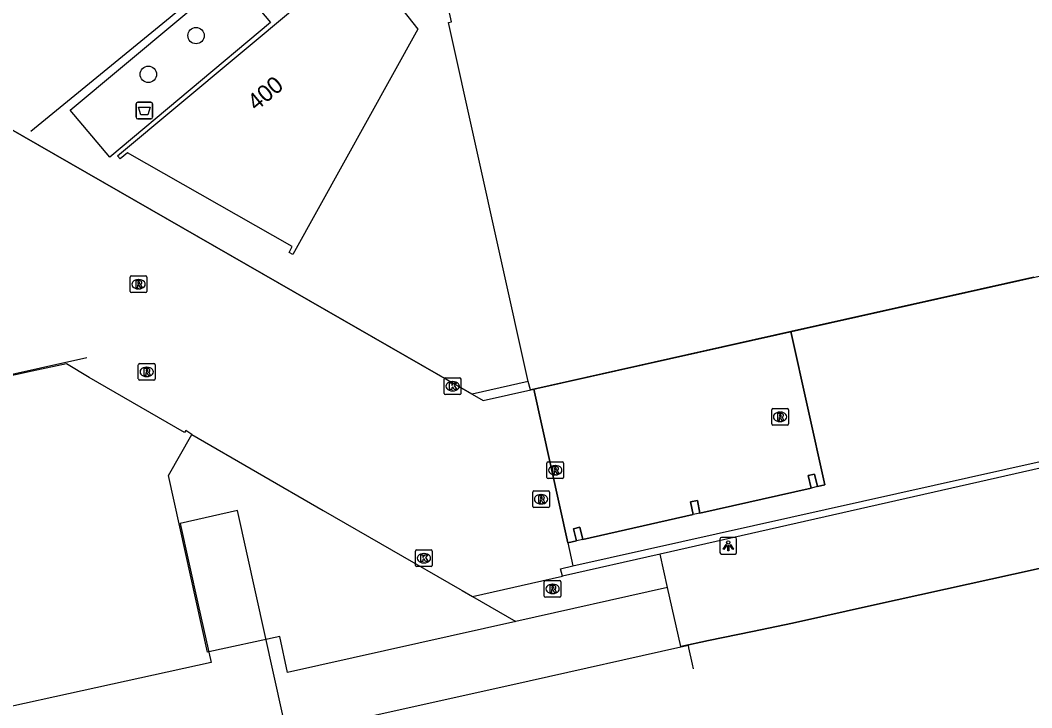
# Model space of a CAD drawing. Extents: x 160806 to 161707, y 383697 to 384148.
# Drawn here: x 161428.9 to 161489.3, y 383818.3 to 383859.4 of the extents above; entities that cross this region are included whole.
import ezdxf

# ---------------------------------------------------------------- set-up
doc = ezdxf.new("R2010")
doc.units = 0
for name, color, linetype in [('IMGEO_Afvalbak', 7, 'Continuous'), ('IMGEO_Boom', 7, 'Continuous'), ('IMGEO_Hek', 7, 'Continuous'), ('IMGEO_Kolk', 7, 'Continuous'), ('IMGEO_Lichtpunt', 7, 'Continuous'), ('IMGEO_Lijnafwatering', 7, 'Continuous'), ('IMGEO_Pand', 7, 'Continuous'), ('IMGEO_Pand_nummerreeks', 7, 'Continuous'), ('IMGEO_Pand_overbouw', 7, 'Continuous'), ('IMGEO_Pand_vergunning_verleend', 7, 'Continuous'), ('IMGEO_Rijbaan_lokaal_gesloten', 7, 'Continuous'), ('IMGEO_Rijbaan_lokaal_open', 7, 'Continuous'), ('IMGEO_Rioolput', 7, 'Continuous'), ('IMGEO_Spoorbaan_halfverhard', 7, 'Continuous'), ('IMGEO_Verkeerseiland_open', 7, 'Continuous'), ('IMGEO_Voetpad_open', 7, 'Continuous')]:
    doc.layers.add(name, color=color, linetype=linetype)

msp = doc.modelspace()

# ---------------------------------------------------------------- linework, layer by layer
at = {"layer": 'IMGEO_Afvalbak'}
for p, q in [((161435.802, 383853.602), (161435.802, 383854.402)), ((161435.802, 383854.402), (161435.802, 383853.602)), ((161435.902, 383854.502), (161436.692, 383854.502)), ((161436.692, 383854.502), (161435.902, 383854.502)), ((161436.792, 383854.402), (161436.792, 383853.602)), ((161436.792, 383853.602), (161436.792, 383854.402)), ((161436.692, 383853.502), (161435.902, 383853.502)), ((161435.902, 383853.502), (161436.692, 383853.502))]:
    msp.add_line(p, q, dxfattribs=at)
msp.add_lwpolyline([(161435.945, 383854.216), (161436.649, 383854.216), (161436.5, 383853.746), (161436.094, 383853.746), (161435.945, 383854.216)], dxfattribs=at)
for centre, start, end in [((161435.902, 383854.402), 90, 180), ((161435.902, 383854.402), 90, 180), ((161436.692, 383854.402), 0, 90), ((161436.692, 383854.402), 360, 90), ((161435.902, 383853.602), 180, 270), ((161435.902, 383853.602), 180, 270), ((161436.692, 383853.602), 270, 0), ((161436.692, 383853.602), 270, 0)]:
    msp.add_arc(centre, 0.1, start, end, dxfattribs=at)
at = {"layer": 'IMGEO_Boom'}
for centre in [(161439.388, 383858.484), (161436.538, 383856.171)]:
    msp.add_circle(centre, 0.489, dxfattribs=at)
at = {"layer": 'IMGEO_Hek'}
for points in [[(161468.352, 383821.972), (161470.021, 383822.345), (161472.634, 383822.879), (161475.023, 383823.371), (161479.934, 383824.467), (161509.272, 383830.942), (161514.217, 383832.035), (161521.635, 383833.723), (161580.201, 383846.689), (161582.51, 383847.687), (161585.012, 383847.75), (161614.342, 383854.325), (161641.301, 383860.274), (161651.06, 383862.411), (161662.497, 383864.892), (161670.593, 383866.669), (161682.93, 383869.376), (161687.731, 383870.454), (161692.46, 383871.911), (161696.167, 383872.737)], [(161439.133, 383834.644), (161446.976, 383830.114), (161455.145, 383825.407)], [(161455.145, 383825.407), (161455.299, 383825.318)], [(161455.299, 383825.318), (161455.916, 383824.962)], [(161455.916, 383824.962), (161458.497, 383823.475)], [(161468.36, 383821.937), (161459.292, 383819.913), (161449.186, 383817.657)]]:
    msp.add_lwpolyline(points, dxfattribs=at)
at = {"layer": 'IMGEO_Kolk'}
for p, q in [((161454.221, 383837.106), (161454.221, 383837.958)), ((161454.296, 383838.032), (161455.148, 383838.032)), ((161454.709, 383837.812), (161454.734, 383837.812)), ((161455.222, 383837.958), (161455.222, 383837.106)), ((161454.732, 383837.252), (161454.707, 383837.252)), ((161455.148, 383837.032), (161454.296, 383837.032)), ((161452.506, 383826.829), (161452.506, 383827.681)), ((161452.581, 383827.755), (161453.433, 383827.755)), ((161452.994, 383827.535), (161453.019, 383827.535)), ((161453.507, 383827.681), (161453.507, 383826.829)), ((161453.017, 383826.975), (161452.992, 383826.975)), ((161453.433, 383826.755), (161452.581, 383826.755))]:
    msp.add_line(p, q, dxfattribs=at)
for points in [[(161454.221, 383837.106), (161454.221, 383837.958)], [(161454.296, 383838.032), (161455.148, 383838.032)], [(161454.542, 383837.732), (161454.665, 383837.732), (161454.665, 383837.581), (161454.795, 383837.732), (161454.959, 383837.732), (161454.813, 383837.581), (161454.966, 383837.332), (161454.814, 383837.332), (161454.729, 383837.496), (161454.665, 383837.429), (161454.665, 383837.332), (161454.542, 383837.332), (161454.542, 383837.732)], [(161455.222, 383837.958), (161455.222, 383837.106)], [(161455.148, 383837.032), (161454.296, 383837.032)], [(161452.506, 383826.829), (161452.506, 383827.681)], [(161452.581, 383827.755), (161453.433, 383827.755)], [(161452.827, 383827.455), (161452.95, 383827.455), (161452.95, 383827.304), (161453.08, 383827.455), (161453.244, 383827.455), (161453.098, 383827.304), (161453.251, 383827.055), (161453.099, 383827.055), (161453.014, 383827.219), (161452.95, 383827.152), (161452.95, 383827.055), (161452.827, 383827.055), (161452.827, 383827.455)], [(161453.507, 383827.681), (161453.507, 383826.829)], [(161453.433, 383826.755), (161452.581, 383826.755)]]:
    msp.add_lwpolyline(points, dxfattribs=at)
for centre, start, end in [((161454.298, 383837.956), 91.55205, 178.44795), ((161454.298, 383837.956), 91.55205, 178.44795), ((161455.146, 383837.956), 1.55205, 88.44795), ((161455.146, 383837.956), 1.55205, 88.44795), ((161454.298, 383837.108), 181.55205, 268.44795), ((161454.298, 383837.108), 181.55205, 268.44795), ((161455.146, 383837.108), 271.55205, 358.44795), ((161455.146, 383837.108), 271.55205, 358.44795), ((161452.583, 383827.679), 91.55205, 178.44795), ((161452.583, 383827.679), 91.55205, 178.44795), ((161453.431, 383827.679), 1.55205, 88.44795), ((161453.431, 383827.679), 1.55205, 88.44795), ((161452.583, 383826.831), 181.55205, 268.44795), ((161452.583, 383826.831), 181.55205, 268.44795), ((161453.431, 383826.831), 271.55205, 358.44795), ((161453.431, 383826.831), 271.55205, 358.44795)]:
    msp.add_arc(centre, 0.0765, start, end, dxfattribs=at)
for centre, major_axis, ratio, start_param, end_param in [((161454.708, 383837.532), (-0.387, 0.002), 0.722429, 4.712389, 7.853982), ((161454.733, 383837.532), (-0.39, 0.002), 0.717154, 1.570796, 4.712389), ((161452.993, 383827.255), (-0.387, 0.002), 0.722429, 4.712389, 7.853982), ((161453.018, 383827.255), (-0.39, 0.002), 0.717154, 1.570796, 4.712389)]:
    msp.add_ellipse(centre, major_axis=major_axis, ratio=ratio, start_param=start_param, end_param=end_param, dxfattribs=at)
at = {"layer": 'IMGEO_Lichtpunt'}
for p, q in [((161470.695, 383828.404), (161470.695, 383827.597)), ((161470.695, 383828.404), (161470.695, 383827.597)), ((161471.597, 383828.499), (161470.789, 383828.499)), ((161471.597, 383828.499), (161470.789, 383828.499)), ((161471.691, 383827.597), (161471.691, 383828.404)), ((161471.691, 383827.597), (161471.691, 383828.404)), ((161470.789, 383827.503), (161471.597, 383827.503)), ((161470.789, 383827.503), (161471.597, 383827.503))]:
    msp.add_line(p, q, dxfattribs=at)
for points in [[(161471.069, 383828.068), (161471.108, 383828.04), (161470.92, 383827.778), (161470.882, 383827.805), (161471.069, 383828.068)], [(161471.171, 383828.02), (161471.218, 383828.02), (161471.218, 383827.698), (161471.171, 383827.698), (161471.171, 383828.02)], [(161471.281, 383828.04), (161471.319, 383828.067), (161471.506, 383827.805), (161471.467, 383827.777), (161471.281, 383828.04)]]:
    msp.add_lwpolyline(points, dxfattribs=at)
msp.add_circle((161471.194, 383828.202), 0.0994, dxfattribs=at)
for centre, start, end in [((161470.789, 383828.404), 90, 180), ((161470.789, 383828.404), 90, 180), ((161471.597, 383828.404), 0, 90), ((161471.597, 383828.404), 0, 90), ((161470.789, 383827.597), 180, 270), ((161470.789, 383827.597), 180, 270), ((161471.597, 383827.597), 270, 0), ((161471.597, 383827.597), 270, 360)]:
    msp.add_arc(centre, 0.0946, start, end, dxfattribs=at)
at = {"layer": 'IMGEO_Lijnafwatering'}
for points in [[(161446.281, 383866.489), (161429.508, 383852.763)], [(161419.351, 383836.25), (161432.862, 383839.245)]]:
    msp.add_lwpolyline(points, dxfattribs=at)
at = {"layer": 'IMGEO_Pand'}
for points in [[(161459.23, 383837.816), (161454.467, 383859.266), (161454.649, 383859.314), (161452.306, 383869.965), (161465.897, 383881.096)], [(161445.17, 383845.408), (161444.948, 383845.529), (161445.128, 383845.88), (161435.296, 383851.477), (161434.859, 383851.112), (161434.699, 383851.304), (161449.115, 383863.351), (161452.644, 383858.861), (161445.17, 383845.408)], [(161489.445, 383844.046), (161474.936, 383840.799)], [(161459.571, 383837.36), (161474.936, 383840.799)], [(161439.133, 383834.644), (161439.136, 383834.65), (161438.779, 383834.879), (161438.695, 383834.766), (161432.999, 383838.061), (161431.64, 383838.863), (161429.594, 383838.43), (161405.826, 383833.211)], [(161459.571, 383837.36), (161459.371, 383837.315), (161459.23, 383837.816)], [(161458.497, 383823.475), (161444.86, 383820.431), (161444.389, 383822.588), (161440.151, 383821.653), (161440.079, 383821.637), (161437.743, 383832.2), (161439.133, 383834.644)], [(161476.528, 383831.533), (161476.347, 383832.284), (161475.96, 383832.191), (161476.142, 383831.439)], [(161476.528, 383831.533), (161476.142, 383831.439)], [(161469.504, 383829.954), (161469.353, 383830.703), (161468.944, 383830.62), (161469.095, 383829.871)], [(161469.504, 383829.954), (161469.095, 383829.871)], [(161462.499, 383828.381), (161462.322, 383829.103), (161461.943, 383829.01), (161462.119, 383828.288)], [(161462.499, 383828.381), (161462.119, 383828.288)], [(161467.565, 383825.499), (161458.497, 383823.475)], [(161468.352, 383821.972), (161467.565, 383825.499)], [(161468.352, 383821.972), (161468.36, 383821.937)], [(161468.36, 383821.937), (161459.292, 383819.913), (161449.186, 383817.657)]]:
    msp.add_lwpolyline(points, dxfattribs=at)
at = {"layer": 'IMGEO_Pand_overbouw'}
for points in [[(161576.544, 383863.524), (161556.299, 383953.974), (161403.923, 383918.874), (161417.58, 383859.039), (161456.542, 383836.683)], [(161476.142, 383831.439), (161475.96, 383832.191), (161476.347, 383832.284), (161476.528, 383831.533), (161476.962, 383831.641), (161474.936, 383840.799), (161459.571, 383837.36), (161461.599, 383828.173), (161462.119, 383828.288), (161461.943, 383829.01), (161462.322, 383829.103), (161462.499, 383828.381), (161469.095, 383829.871), (161468.944, 383830.62), (161469.353, 383830.703), (161469.504, 383829.954)], [(161445.142, 383815.339), (161441.873, 383830.1), (161438.438, 383829.334), (161439.521, 383824.478), (161440.29, 383821.029), (161419.78, 383816.517), (161421.083, 383810.599), (161402.46, 383805.86), (161402.903, 383803.833), (161432.009, 383812.432)]]:
    msp.add_lwpolyline(points, close=True, dxfattribs=at)
at = {"layer": 'IMGEO_Pand_vergunning_verleend'}
msp.add_lwpolyline([(161431.877, 383854.037), (161441.49, 383862.083), (161443.842, 383859.273), (161434.229, 383851.226), (161431.877, 383854.037)], dxfattribs=at)
at = {"layer": 'IMGEO_Rijbaan_lokaal_gesloten'}
for points in [[(161461.912, 383826.794), (161498.576, 383834.978), (161578.911, 383853.047)], [(161474.936, 383840.799), (161476.962, 383831.641), (161476.528, 383831.533)], [(161476.142, 383831.439), (161469.504, 383829.954)], [(161469.095, 383829.871), (161462.499, 383828.381)], [(161462.119, 383828.288), (161461.599, 383828.173)], [(161461.599, 383828.173), (161461.912, 383826.794)]]:
    msp.add_lwpolyline(points, dxfattribs=at)
at = {"layer": 'IMGEO_Rijbaan_lokaal_open'}
for points in [[(161459.23, 383837.816), (161455.886, 383837.059), (161417.58, 383859.039), (161418.734, 383860.447)], [(161461.599, 383828.173), (161459.571, 383837.36)], [(161439.133, 383834.644), (161446.976, 383830.114), (161455.145, 383825.407), (161455.299, 383825.318), (161455.916, 383824.962)], [(161461.28, 383826.175), (161461.178, 383826.63), (161461.912, 383826.794)], [(161455.916, 383824.962), (161461.28, 383826.175)]]:
    msp.add_lwpolyline(points, dxfattribs=at)
at = {"layer": 'IMGEO_Rioolput'}
for p, q in [((161435.451, 383843.201), (161435.451, 383844.053)), ((161435.526, 383844.127), (161436.378, 383844.127)), ((161435.939, 383843.907), (161435.964, 383843.907)), ((161436.452, 383844.053), (161436.452, 383843.201)), ((161436.378, 383843.127), (161435.526, 383843.127)), ((161435.962, 383843.347), (161435.937, 383843.347)), ((161436.016, 383838.892), (161436.868, 383838.892)), ((161435.941, 383837.966), (161435.941, 383838.818)), ((161436.429, 383838.672), (161436.454, 383838.672)), ((161436.942, 383838.818), (161436.942, 383837.966)), ((161436.868, 383837.892), (161436.016, 383837.892)), ((161436.452, 383838.112), (161436.427, 383838.112)), ((161473.791, 383835.279), (161473.791, 383836.131)), ((161473.866, 383836.205), (161474.718, 383836.205)), ((161474.279, 383835.985), (161474.304, 383835.985)), ((161474.792, 383836.131), (161474.792, 383835.279)), ((161474.302, 383835.425), (161474.277, 383835.425)), ((161474.718, 383835.205), (161473.866, 383835.205)), ((161460.351, 383832.087), (161460.351, 383832.939)), ((161460.426, 383833.013), (161461.278, 383833.013)), ((161461.352, 383832.939), (161461.352, 383832.087)), ((161460.862, 383832.233), (161460.837, 383832.233)), ((161460.839, 383832.793), (161460.864, 383832.793)), ((161461.278, 383832.013), (161460.426, 383832.013)), ((161459.508, 383830.353), (161459.508, 383831.205)), ((161459.583, 383831.279), (161460.435, 383831.279)), ((161459.996, 383831.059), (161460.021, 383831.059)), ((161460.509, 383831.205), (161460.509, 383830.353)), ((161460.019, 383830.499), (161459.994, 383830.499)), ((161460.435, 383830.279), (161459.583, 383830.279)), ((161460.196, 383824.999), (161460.196, 383825.851)), ((161460.271, 383825.925), (161461.123, 383825.925)), ((161460.684, 383825.705), (161460.709, 383825.705)), ((161461.197, 383825.851), (161461.197, 383824.999)), ((161460.707, 383825.145), (161460.682, 383825.145)), ((161461.123, 383824.925), (161460.271, 383824.925))]:
    msp.add_line(p, q, dxfattribs=at)
for points in [[(161435.451, 383843.201), (161435.451, 383844.053)], [(161435.526, 383844.127), (161436.378, 383844.127)], [(161436.04, 383843.825), (161435.788, 383843.827), (161435.788, 383843.427)], [(161435.966, 383843.746), (161435.912, 383843.746), (161435.912, 383843.665)], [(161436.452, 383844.053), (161436.452, 383843.201)], [(161436.378, 383843.127), (161435.526, 383843.127)], [(161435.788, 383843.427), (161435.912, 383843.427), (161435.912, 383843.589), (161435.923, 383843.589)], [(161435.912, 383843.665), (161435.964, 383843.665)], [(161435.97, 383843.56), (161436.041, 383843.427), (161436.181, 383843.427), (161436.116, 383843.553)], [(161436.016, 383838.892), (161436.868, 383838.892)], [(161435.941, 383837.966), (161435.941, 383838.818)], [(161436.53, 383838.59), (161436.278, 383838.592), (161436.278, 383838.192)], [(161436.278, 383838.192), (161436.402, 383838.192), (161436.402, 383838.354), (161436.413, 383838.354)], [(161436.456, 383838.511), (161436.402, 383838.511), (161436.402, 383838.43)], [(161436.402, 383838.43), (161436.454, 383838.43)], [(161436.46, 383838.325), (161436.531, 383838.192), (161436.671, 383838.192), (161436.606, 383838.318)], [(161436.942, 383838.818), (161436.942, 383837.966)], [(161436.868, 383837.892), (161436.016, 383837.892)], [(161473.791, 383835.279), (161473.791, 383836.131)], [(161473.866, 383836.205), (161474.718, 383836.205)], [(161474.38, 383835.903), (161474.128, 383835.905), (161474.128, 383835.505)], [(161474.792, 383836.131), (161474.792, 383835.279)], [(161474.128, 383835.505), (161474.252, 383835.505), (161474.252, 383835.667), (161474.263, 383835.667)], [(161474.306, 383835.824), (161474.252, 383835.824), (161474.252, 383835.743)], [(161474.252, 383835.743), (161474.304, 383835.743)], [(161474.31, 383835.638), (161474.381, 383835.505), (161474.521, 383835.505), (161474.456, 383835.631)], [(161474.718, 383835.205), (161473.866, 383835.205)], [(161460.351, 383832.087), (161460.351, 383832.939)], [(161460.426, 383833.013), (161461.278, 383833.013)], [(161461.352, 383832.939), (161461.352, 383832.087)], [(161460.94, 383832.711), (161460.688, 383832.713), (161460.688, 383832.313)], [(161460.688, 383832.313), (161460.812, 383832.313), (161460.812, 383832.475), (161460.823, 383832.475)], [(161460.866, 383832.632), (161460.812, 383832.632), (161460.812, 383832.551)], [(161460.812, 383832.551), (161460.864, 383832.551)], [(161460.87, 383832.446), (161460.941, 383832.313), (161461.081, 383832.313), (161461.016, 383832.439)], [(161461.278, 383832.013), (161460.426, 383832.013)], [(161459.508, 383830.353), (161459.508, 383831.205)], [(161459.583, 383831.279), (161460.435, 383831.279)], [(161460.509, 383831.205), (161460.509, 383830.353)], [(161460.097, 383830.977), (161459.845, 383830.979), (161459.845, 383830.579)], [(161459.845, 383830.579), (161459.969, 383830.579), (161459.969, 383830.741), (161459.98, 383830.741)], [(161460.023, 383830.898), (161459.969, 383830.898), (161459.969, 383830.817)], [(161459.969, 383830.817), (161460.021, 383830.817)], [(161460.027, 383830.712), (161460.098, 383830.579), (161460.238, 383830.579), (161460.173, 383830.705)], [(161460.435, 383830.279), (161459.583, 383830.279)], [(161460.196, 383824.999), (161460.196, 383825.851)], [(161460.271, 383825.925), (161461.123, 383825.925)], [(161460.785, 383825.623), (161460.533, 383825.625), (161460.533, 383825.225)], [(161461.197, 383825.851), (161461.197, 383824.999)], [(161460.533, 383825.225), (161460.657, 383825.225), (161460.657, 383825.387), (161460.668, 383825.387)], [(161460.711, 383825.544), (161460.657, 383825.544), (161460.657, 383825.463)], [(161460.657, 383825.463), (161460.709, 383825.463)], [(161460.715, 383825.358), (161460.786, 383825.225), (161460.926, 383825.225), (161460.861, 383825.351)], [(161461.123, 383824.925), (161460.271, 383824.925)]]:
    msp.add_lwpolyline(points, dxfattribs=at)
for centre, radius, start, end in [((161435.528, 383844.051), 0.0765, 91.55205, 178.44795), ((161435.528, 383844.051), 0.0765, 91.55205, 178.44795), ((161435.972, 383843.65), 0.0964, 77.00612, 93.18647), ((161435.986, 383843.707), 0.0378, 276.66336, 79.67722), ((161436.039, 383843.715), 0.109, 350.36119, 89.41601), ((161436.376, 383844.051), 0.0765, 1.55205, 88.44795), ((161436.376, 383844.051), 0.0765, 1.55205, 88.44795), ((161435.528, 383843.203), 0.0765, 181.55205, 268.44795), ((161435.528, 383843.203), 0.0765, 181.55205, 268.44795), ((161435.922, 383843.536), 0.0533, 26.02933, 88.69889), ((161435.948, 383843.854), 0.19, 274.7715, 282.96867), ((161436.037, 383843.715), 0.112, 277.58423, 350.98172), ((161436.021, 383843.5), 0.108, 29.51342, 73.79051), ((161436.376, 383843.203), 0.0765, 271.55205, 358.44795), ((161436.376, 383843.203), 0.0765, 271.55205, 358.44795), ((161436.018, 383838.816), 0.0765, 91.55205, 178.44795), ((161436.018, 383838.816), 0.0765, 91.55205, 178.44795), ((161436.866, 383838.816), 0.0765, 1.55205, 88.44795), ((161436.866, 383838.816), 0.0765, 1.55205, 88.44795), ((161436.412, 383838.301), 0.0533, 26.02933, 88.69889), ((161436.438, 383838.619), 0.19, 274.7715, 282.96867), ((161436.462, 383838.415), 0.0964, 77.00612, 93.18647), ((161436.476, 383838.472), 0.0378, 276.66336, 79.67722), ((161436.529, 383838.48), 0.109, 350.36119, 89.41601), ((161436.527, 383838.48), 0.112, 277.58423, 350.98172), ((161436.511, 383838.265), 0.108, 29.51342, 73.79051), ((161436.018, 383837.968), 0.0765, 181.55205, 268.44795), ((161436.018, 383837.968), 0.0765, 181.55205, 268.44795), ((161436.866, 383837.968), 0.0765, 271.55205, 358.44795), ((161436.866, 383837.968), 0.0765, 271.55205, 358.44795), ((161473.868, 383836.129), 0.0765, 91.55205, 178.44795), ((161473.868, 383836.129), 0.0765, 91.55205, 178.44795), ((161474.379, 383835.793), 0.109, 350.36119, 89.41601), ((161474.716, 383836.129), 0.0765, 1.55205, 88.44795), ((161474.716, 383836.129), 0.0765, 1.55205, 88.44795), ((161473.868, 383835.281), 0.0765, 181.55205, 268.44795), ((161473.868, 383835.281), 0.0765, 181.55205, 268.44795), ((161474.262, 383835.614), 0.0533, 26.02933, 88.69889), ((161474.288, 383835.932), 0.19, 274.7715, 282.96867), ((161474.312, 383835.728), 0.0964, 77.00612, 93.18647), ((161474.326, 383835.785), 0.0378, 276.66336, 79.67722), ((161474.377, 383835.793), 0.112, 277.58423, 350.98172), ((161474.361, 383835.578), 0.108, 29.51342, 73.79051), ((161474.716, 383835.281), 0.0765, 271.55205, 358.44795), ((161474.716, 383835.281), 0.0765, 271.55205, 358.44795), ((161460.428, 383832.937), 0.0765, 91.55205, 178.44795), ((161460.428, 383832.937), 0.0765, 91.55205, 178.44795), ((161461.276, 383832.937), 0.0765, 1.55205, 88.44795), ((161461.276, 383832.937), 0.0765, 1.55205, 88.44795), ((161460.822, 383832.422), 0.0533, 26.02933, 88.69889), ((161460.848, 383832.74), 0.19, 274.7715, 282.96867), ((161460.872, 383832.536), 0.0964, 77.00612, 93.18647), ((161460.886, 383832.593), 0.0378, 276.66336, 79.67722), ((161460.939, 383832.601), 0.109, 350.36119, 89.41601), ((161460.937, 383832.601), 0.112, 277.58423, 350.98172), ((161460.921, 383832.386), 0.108, 29.51342, 73.79051), ((161460.428, 383832.089), 0.0765, 181.55205, 268.44795), ((161460.428, 383832.089), 0.0765, 181.55205, 268.44795), ((161461.276, 383832.089), 0.0765, 271.55205, 358.44795), ((161461.276, 383832.089), 0.0765, 271.55205, 358.44795), ((161459.585, 383831.203), 0.0765, 91.55205, 178.44795), ((161459.585, 383831.203), 0.0765, 91.55205, 178.44795), ((161460.433, 383831.203), 0.0765, 1.55205, 88.44795), ((161460.433, 383831.203), 0.0765, 1.55205, 88.44795), ((161459.979, 383830.688), 0.0533, 26.02933, 88.69889), ((161460.005, 383831.006), 0.19, 274.7715, 282.96867), ((161460.029, 383830.802), 0.0964, 77.00612, 93.18647), ((161460.043, 383830.859), 0.0378, 276.66336, 79.67722), ((161460.096, 383830.867), 0.109, 350.36119, 89.41601), ((161460.094, 383830.867), 0.112, 277.58423, 350.98172), ((161460.078, 383830.652), 0.108, 29.51342, 73.79051), ((161459.585, 383830.355), 0.0765, 181.55205, 268.44795), ((161459.585, 383830.355), 0.0765, 181.55205, 268.44795), ((161460.433, 383830.355), 0.0765, 271.55205, 358.44795), ((161460.433, 383830.355), 0.0765, 271.55205, 358.44795), ((161460.273, 383825.849), 0.0765, 91.55205, 178.44795), ((161460.273, 383825.849), 0.0765, 91.55205, 178.44795), ((161460.784, 383825.513), 0.109, 350.36119, 89.41601), ((161461.121, 383825.849), 0.0765, 1.55205, 88.44795), ((161461.121, 383825.849), 0.0765, 1.55205, 88.44795), ((161460.273, 383825.001), 0.0765, 181.55205, 268.44795), ((161460.273, 383825.001), 0.0765, 181.55205, 268.44795), ((161460.667, 383825.334), 0.0533, 26.02933, 88.69889), ((161460.693, 383825.652), 0.19, 274.7715, 282.96867), ((161460.717, 383825.448), 0.0964, 77.00612, 93.18647), ((161460.731, 383825.505), 0.0378, 276.66336, 79.67722), ((161460.782, 383825.513), 0.112, 277.58423, 350.98172), ((161460.766, 383825.298), 0.108, 29.51342, 73.79051), ((161461.121, 383825.001), 0.0765, 271.55205, 358.44795), ((161461.121, 383825.001), 0.0765, 271.55205, 358.44795)]:
    msp.add_arc(centre, radius, start, end, dxfattribs=at)
for centre, major_axis, ratio, start_param, end_param in [((161435.938, 383843.627), (-0.387, 0.002), 0.722429, 4.712389, 7.853982), ((161435.963, 383843.627), (-0.39, 0.002), 0.717154, 1.570796, 4.712389), ((161436.428, 383838.392), (-0.387, 0.002), 0.722429, 4.712389, 7.853982), ((161436.453, 383838.392), (-0.39, 0.002), 0.717154, 1.570796, 4.712389), ((161474.278, 383835.705), (-0.387, 0.002), 0.722429, 4.712389, 7.853982), ((161474.303, 383835.705), (-0.39, 0.002), 0.717154, 1.570796, 4.712389), ((161460.838, 383832.513), (-0.387, 0.002), 0.722429, 4.712389, 7.853982), ((161460.863, 383832.513), (-0.39, 0.002), 0.717154, 1.570796, 4.712389), ((161459.995, 383830.779), (-0.387, 0.002), 0.722429, 4.712389, 7.853982), ((161460.02, 383830.779), (-0.39, 0.002), 0.717154, 1.570796, 4.712389), ((161460.683, 383825.425), (-0.387, 0.002), 0.722429, 4.712389, 7.853982), ((161460.708, 383825.425), (-0.39, 0.002), 0.717154, 1.570796, 4.712389)]:
    msp.add_ellipse(centre, major_axis=major_axis, ratio=ratio, start_param=start_param, end_param=end_param, dxfattribs=at)
at = {"layer": 'IMGEO_Spoorbaan_halfverhard'}
for points in [[(161670.593, 383866.669), (161662.497, 383864.892), (161651.06, 383862.411), (161641.301, 383860.274), (161614.342, 383854.325), (161585.012, 383847.75), (161582.51, 383847.687), (161580.201, 383846.689), (161521.635, 383833.723), (161514.217, 383832.035), (161509.272, 383830.942), (161479.934, 383824.467), (161475.023, 383823.371), (161472.634, 383822.879), (161470.021, 383822.345), (161468.352, 383821.972)], [(161469.119, 383820.647), (161469.057, 383820.924), (161468.839, 383821.9), (161468.808, 383822.037), (161468.36, 383821.937)]]:
    msp.add_lwpolyline(points, dxfattribs=at)
at = {"layer": 'IMGEO_Verkeerseiland_open'}
msp.add_lwpolyline([(161587.517, 383854.389), (161587.103, 383854.297), (161573.981, 383851.379), (161498.641, 383834.626), (161467.119, 383827.496)], dxfattribs=at)
at = {"layer": 'IMGEO_Voetpad_open'}
for points in [[(161467.119, 383827.496), (161461.28, 383826.175)], [(161467.565, 383825.499), (161467.119, 383827.496)], [(161455.916, 383824.962), (161458.497, 383823.475)]]:
    msp.add_lwpolyline(points, dxfattribs=at)

# ---------------------------------------------------------------- texts
at = {"layer": 'IMGEO_Pand_nummerreeks'}
msp.add_text('400', height=1, rotation=39.79702, dxfattribs=at).set_placement((161442.98, 383853.945))

doc.saveas('drawing.dxf')
